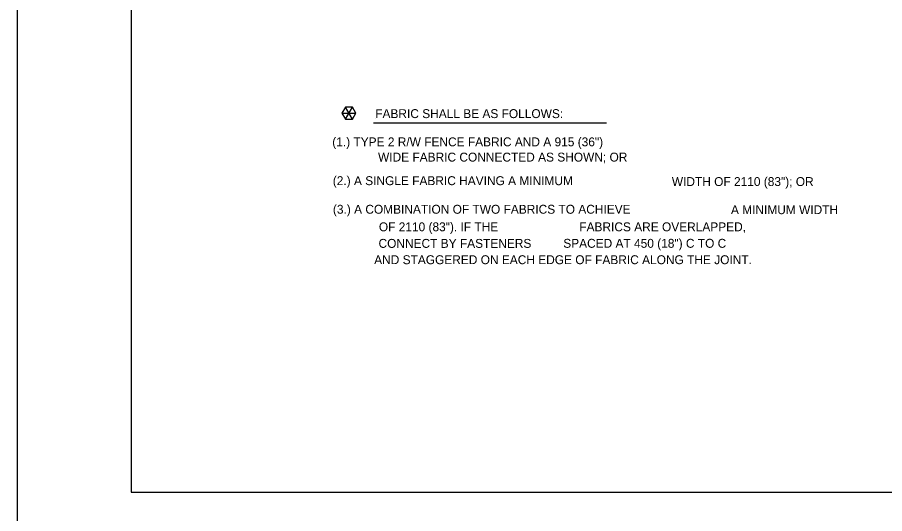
# Model space of a CAD drawing. Extents: x 13 to 918, y -903 to 879.
# Drawn here: x 13.3 to 317.7, y 292.4 to 466.7 of the extents above; entities that cross this region are included whole.
import ezdxf

# ---------------------------------------------------------------- set-up
doc = ezdxf.new("R2010")
doc.units = 0
for name, color, linetype in [('1', 7, 'Continuous'), ('2', 7, 'Continuous'), ('3', 7, 'Continuous'), ('PLT-BNDY', 7, 'Continuous')]:
    doc.layers.add(name, color=color, linetype=linetype)

msp = doc.modelspace()

# ---------------------------------------------------------------- linework, layer by layer
at = {"layer": '1'}
msp.add_line((138.262, 429.6155), (219.989, 429.6155), dxfattribs=at)
msp.add_lwpolyline([(839.2505, 299.93025), (839.2505, 863.93025), (53.2505, 863.93025), (53.2505, 299.93025), (839.2505, 299.93025), (839.2505, 326.28925), (639.2505, 326.28925), (639.2505, 390.96675), (839.2505, 390.96675), (839.2505, 419.93025), (639.2505, 419.93025), (639.2505, 299.93025), (718.052, 299.93025), (718.052, 326.28925), (718.052, 299.93025), (795.052, 299.93025), (795.052, 326.28925), (795.052, 313.97275), (839.2505, 313.97275)], dxfattribs=at)
at = {"layer": '2'}
msp.add_line((138.87825, 431.28875), (138.87825, 431.28875), dxfattribs=at)
at = {"layer": '3'}
for p, q in [((127.16775, 433.03875), (132.05325, 433.03875)), ((128.3885, 430.92425), (130.83225, 435.1555)), ((130.83225, 430.92425), (128.3885, 435.1555))]:
    msp.add_line(p, q, dxfattribs=at)
msp.add_lwpolyline([(128.3885, 430.92425), (130.83225, 430.92425), (132.05325, 433.03875), (130.83225, 435.1555), (128.3885, 435.1555), (127.16775, 433.03875)], close=True, dxfattribs=at)
at = {"layer": 'PLT-BNDY'}
msp.add_lwpolyline([(13.2505, 878.93025), (854.2505, 878.93025), (854.2505, 284.93025), (13.2505, 284.93025)], close=True, dxfattribs=at)

# ---------------------------------------------------------------- texts
at = {"layer": '3'}
for s, p in [('FABRIC SHALL BE AS FOLLOWS:', (138.87825, 431.28875)), ('(1.) TYPE 2 R/W FENCE FABRIC AND A 915 (36")', (123.79075, 421.3805)), ('WIDE FABRIC CONNECTED AS SHOWN; OR', (139.85325, 416.02825)), ('(2.) A SINGLE FABRIC HAVING A MINIMUM', (123.97375, 407.75125)), ('WIDTH OF 2110 (83"); OR', (242.97825, 407.44075)), ('(3.) A COMBINATION OF TWO FABRICS TO ACHIEVE', (124.01975, 397.713)), ('A MINIMUM WIDTH ', (263.7295, 397.57325)), ('OF 2110 (83"). IF THE', (140.15175, 391.5565)), ('FABRICS ARE OVERLAPPED,', (210.50025, 391.5525)), ('CONNECT BY FASTENERS', (140.031, 385.74225)), ('SPACED AT 450 (18") C TO C', (204.86625, 385.76275)), (' AND STAGGERED ON EACH EDGE OF FABRIC ALONG THE JOINT.', (137.343, 380.01075))]:
    msp.add_text(s, height=3.1249995, dxfattribs=at).set_placement(p)

doc.saveas('drawing.dxf')
